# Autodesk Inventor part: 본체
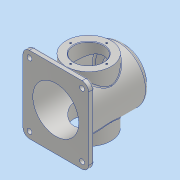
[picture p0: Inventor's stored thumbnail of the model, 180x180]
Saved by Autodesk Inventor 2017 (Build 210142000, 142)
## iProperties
Part Number: 본체
Material: 알루미늄 6061
Document SubType Name: Modeling
Designer: MRC
Density: 2.7 g/cm^3
Appearance: 알루미늄 - 평지
Mass: 1235.53 g
Surface Area: 1067.6 cm^2
Volume: 457.603 cm^3
Author: MRC
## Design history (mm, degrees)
sketch "스케치1"
  geometry: C1 r 50 at (0, 0); 1 further point
  constraints: 1 centre point, 1 coincident
  dimensions: "d2" = 100 diameter of C1
extrude "돌출1" new body sketch "스케치1" stored distance "d0" = 120; taper "d1" = 0 deg
sketch "스케치2"
  geometry: L1 (60, 70)-(-60, 70); L2 (-60, 70)-(-60, -70); L3 (-60, -70)-(60, -70); L4 (60, -70)-(60, 70); L5 (60, 70)-(-60, -70); L6 (-60, 70)-(60, -70); C1 r 50 at (0, 0) reference
  constraints: 12 end point, 2 midpoint, 2 parallel, 1 horizontal, 1 perpendicular
  dimensions: "d3" = 120 distance of L3.end L2.end; "d4" = 140 distance of L2.end L1.end
extrude "돌출2" join sketch "스케치2" distance "d5" = 10; taper "d6" = 0 deg
sketch "스케치3"
  geometry: C1 r 50 at (0, 0) reference; C2 r 41 at (0, 0)
  constraints: 1 centre point, 1 coincident
  dimensions: "d7" = 82 diameter of C2
extrude "돌출3" join sketch "스케치3" distance "d8" = 5; taper "d9" = 0 deg
sketch "스케치4"
  geometry: C1 r 41 at (0, 0); 1 further point
  constraints: 1 centre point, 1 coincident
  dimensions: "d10" = 82 diameter of C1
extrude "돌출4" join sketch "스케치4" stored distance "d11" = 118; taper "d12" = 0 deg
sketch "스케치5"
  geometry: C1 r 41 at (0, 0) reference; C2 r 27 at (0, 0)
  constraints: 1 centre point, 1 coincident
  dimensions: "d13" = 54 diameter of C2
extrude "돌출5" cut sketch "스케치5" stored distance "d14" = 118; taper "d15" = 0 deg
sketch "스케치6"
  geometry: C1 r 42 at (0, 0); 1 further point
  constraints: 1 centre point, 1 coincident
  dimensions: "d16" = 84 diameter of C1
extrude "돌출6" cut sketch "스케치6" distance "d17" = 112; taper "d18" = 0 deg
sketch "스케치7"
  geometry: C1 r 42 at (0, 0) reference; C2 r 27 at (0, 0)
  constraints: 1 centre point, 1 coincident
  dimensions: "d19" = 54 diameter of C2
extrude "돌출7" cut sketch "스케치7" distance "d20" = 13; taper "d21" = 0 deg
sketch "스케치8"
  geometry: 1 further point
hole "구멍1" sketch "스케치8" at (0, 33) diameter "d23" = 3.242; stored, may be unused: countersink angle "d27" = 90 deg, drill point angle "d29" = 118 deg; dims "d24" = 8, "d25" = 4, "d26" = 2, "d28" = 10
sketch "스케치9"
  geometry: C1 r 1.621 at (0, 33) reference; 1 further point
  constraints: 1 coincident
hole "구멍2" sketch "스케치9" at (0, 33) diameter "d34" = 3.242; stored, may be unused: countersink angle "d38" = 90 deg, drill point angle "d40" = 118 deg; dims "d35" = 8, "d36" = 4, "d37" = 2, "d39" = 10
sketch "스케치10" dims "d44" = 66
  geometry: C1 r 27 at (0, 0) reference; C2 r 41 at (0, 0) reference; 2 further points
  constraints: 2 horizontal alignment, 1 coincident, 2 other
hole "구멍3" sketch "스케치10" at (-33, 0) diameter "d45" = 3.242; stored, may be unused: countersink angle "d49" = 90 deg, drill point angle "d51" = 118 deg; dims "d46" = 8, "d47" = 4, "d48" = 2, "d50" = 10
fillet "모깎기1" dims "d55" = 12
fillet "모깎기2" dims "d56" = 6
fillet "모깎기3" dims "d57" = 3
chamfer "모따기1" distance "d58" = 1; stored, may be unused: second distance "d59" = 2, angle "d60" = 45 deg
node "작업 평면1"
sketch "스케치12"
  geometry: L1 (60, 58)-(60, -58) reference; 2 further points
  constraints: 1 horizontal alignment, 1 other
  dimensions: "d61" = 66 distance from line of L1 point (-6, 0)
feature "엠보싱1" sketch "스케치12" dims "d10" = 82, "d62" = 0.5, "d63" = 0
sketch "스케치13"
  geometry: A1 r 9 centre (48, 58) between (57, 58) and (48, 67) reference; A2 r 9 centre (-48, 58) between (-48, 67) and (-57, 58) reference; A3 r 9 centre (-48, -58) between (-57, -58) and (-48, -67) reference; A4 r 9 centre (48, -58) between (48, -67) and (57, -58) reference; 4 further points
  constraints: 4 coincident
hole "구멍4" sketch "스케치13" at (48, 58), (48, -58), (-48, -58), (-48, 58) diameter "d65" = 9; stored, may be unused: countersink angle "d69" = 90 deg, drill point angle "d71" = 0 deg; dims "d66" = 8, "d67" = 4, "d68" = 2, "d70" = 9
node "솔리드1"
pattern_circular "원형 패턴1" dims angle "d31" = 360 deg
pattern_circular "원형 패턴2" dims angle "d42" = 360 deg
pattern_circular "원형 패턴3" dims angle "d53" = 360 deg
